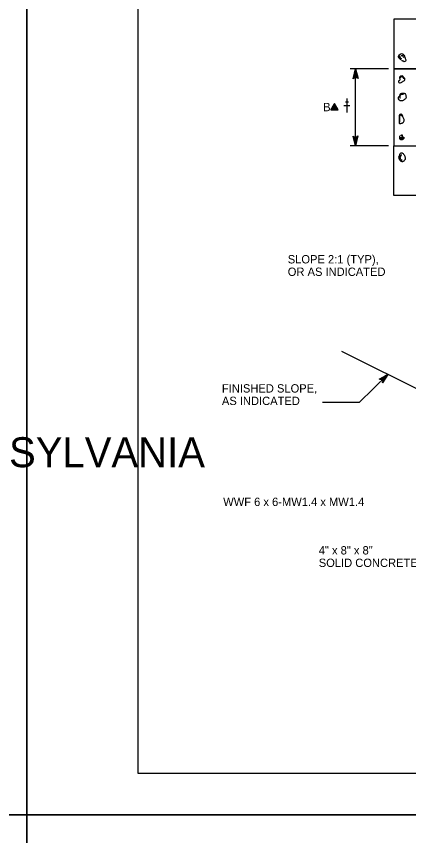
# Model space of a CAD drawing. Extents: x 636183 to 639890, y 299162 to 300538.
# Drawn here: x 638140.2 to 638281.4, y 299936.9 to 300231.9 of the extents above; entities that cross this region are included whole.
import ezdxf

# ---------------------------------------------------------------- set-up
doc = ezdxf.new("R2010")
doc.units = 0
for name, color, linetype in [('1', 7, 'Continuous'), ('Default', 7, 'Continuous'), ('PLT-BNDY', 7, 'Continuous')]:
    doc.layers.add(name, color=color, linetype=linetype)

# ---------------------------------------------------------------- blocks, each defined once
blk = doc.blocks.new('CT')
at = {"layer": 'Default'}
for p, q in [((-0.09, -0.28), (-0.27, 0.03)), ((-0.05, -0.28), (-0.25, 0.07)), ((-0.01, -0.28), (-0.23, 0.1)), ((0.03, -0.28), (-0.21, 0.14)), ((0.07, -0.28), (-0.19, 0.17)), ((0.11, -0.28), (-0.17, 0.21)), ((0.15, -0.28), (-0.15, 0.24)), ((0.19, -0.28), (-0.13, 0.28)), ((0.24, -0.28), (-0.11, 0.32)), ((0.28, -0.28), (-0.09, 0.35)), ((0.32, -0.28), (-0.07, 0.39)), ((0.36, -0.28), (-0.04, 0.42)), ((0.4, -0.28), (-0.02, 0.46)), ((0.44, -0.28), (0, 0.49)), ((-0.42, -0.28), (-0.44, -0.26)), ((-0.38, -0.28), (-0.42, -0.22)), ((-0.34, -0.28), (-0.39, -0.18)), ((-0.3, -0.28), (-0.37, -0.15)), ((-0.26, -0.28), (-0.35, -0.11)), ((-0.22, -0.28), (-0.33, -0.08)), ((-0.18, -0.28), (-0.31, -0.04)), ((-0.14, -0.28), (-0.29, -0.01))]:
    blk.add_line(p, q, dxfattribs=at)
blk.add_lwpolyline([(-0.45, -0.28), (0.44, -0.28), (0, 0.5)], close=True, dxfattribs=at)
blk = doc.blocks.new('CROSS')
at = {"layer": 'Default'}
for p, q in [((-0.182, 0), (0, 0)), ((-0.096, 0.218), (0, 0.218)), ((0, 0.436), (0, -0.435)), ((0, 0.436), (0, 0)), ((0, 0.218), (0.096, 0.218)), ((0, 0), (0.182, 0))]:
    blk.add_line(p, q, dxfattribs=at)

msp = doc.modelspace()

# ---------------------------------------------------------------- linework, layer by layer
at = {"layer": '1'}
msp.add_lwpolyline([(638969.91, 299959.45), (638969.91, 300523.45), (638183.91, 300523.45), (638183.91, 299959.45), (638969.91, 299959.45), (638969.91, 299985.81), (638769.91, 299985.81), (638769.91, 300050.49), (638969.91, 300050.49), (638969.91, 300079.45), (638769.91, 300079.45), (638769.91, 299959.45), (638848.72, 299959.45), (638848.72, 299985.81), (638848.72, 299959.45), (638925.72, 299959.45), (638925.72, 299985.81), (638925.72, 299973.49), (638969.91, 299973.49)], dxfattribs=at)
at = {"layer": 'Default'}
for p, q in [((638274.19, 300212.96), (638260.38, 300212.96)), ((638274.19, 300185.33), (638260.38, 300185.33)), ((638257.27, 300111.36), (638344.64, 300067.68))]:
    msp.add_line(p, q, dxfattribs=at)
for points in [[(638276.12, 300230.92), (638276.12, 300212.96), (638439.16, 300212.96), (638439.16, 300230.92), (638276.12, 300230.92)], [(638261.7, 300209.72), (638261.48, 300209.45), (638262.31, 300212.96), (638261.7, 300209.72), (638262.07, 300209.92), (638262.31, 300212.96), (638262.59, 300209.93), (638262.97, 300209.75), (638262.31, 300212.96), (638263.22, 300209.47), (638262.97, 300209.75)], [(638262.31, 300185.33), (638262.31, 300212.96)], [(638276.12, 300212.96), (638276.12, 300185.33), (638439.16, 300185.33), (638439.16, 300212.96), (638276.12, 300212.96)], [(638262.93, 300188.56), (638263.15, 300188.83), (638262.31, 300185.33), (638262.93, 300188.56), (638262.56, 300188.36), (638262.31, 300185.33), (638262.03, 300188.35), (638261.66, 300188.53), (638262.31, 300185.33), (638261.4, 300188.81), (638261.66, 300188.53)], [(638276.12, 300167.36), (638276.12, 300185.33), (638439.16, 300185.33), (638439.16, 300167.36), (638276.12, 300167.36)], [(638273.98, 300103.01), (638263.58, 300092.92), (638250.36, 300092.92)], [(638271.19, 300101.25), (638270.85, 300101.22), (638273.98, 300103.01), (638271.19, 300101.25), (638271.59, 300101.11), (638273.98, 300103.01), (638271.96, 300100.74), (638272.09, 300100.34), (638273.98, 300103.01), (638272.06, 300099.96), (638272.09, 300100.34)]]:
    msp.add_lwpolyline(points, dxfattribs=at)
for points, degree in [([(638278.67, 300216.24), (638278.37, 300216.43), (638278.14, 300216.68), (638277.94, 300216.97), (638277.77, 300217.23), (638277.79, 300217.61), (638277.94, 300217.88), (638278.03, 300218.04), (638278.16, 300218.16), (638278.31, 300218.25), (638278.63, 300218.44), (638279.11, 300218.51), (638279.4, 300218.25), (638279.8, 300217.89), (638279.97, 300217.43), (638280.13, 300216.97), (638280.27, 300216.58), (638280.49, 300215.94), (638280.13, 300215.69), (638279.87, 300215.51), (638279.5, 300215.75), (638279.22, 300215.88), (638279.1, 300215.94), (638278.97, 300215.99), (638278.86, 300216.06)], 3), ([(638278.92, 300216.59), (638278.69, 300216.73), (638278.51, 300216.92), (638278.36, 300217.15), (638278.26, 300217.3), (638278.27, 300217.54), (638278.36, 300217.71), (638278.37, 300217.72), (638278.37, 300217.72), (638278.38, 300217.73)], 3), ([(638278.76, 300217.83), (638278.89, 300217.85), (638279.03, 300217.91), (638279.16, 300217.83), (638279.41, 300217.66), (638279.45, 300217.38), (638279.56, 300217.13)], 3), ([(638279.13, 300210.53), (638279.31, 300210.41), (638279.44, 300210.26), (638279.58, 300210.08), (638279.8, 300209.79), (638280.06, 300209.47), (638280.03, 300209.18), (638279.99, 300208.82), (638279.48, 300208.54), (638279.13, 300208.29), (638278.76, 300208.03), (638277.98, 300207.94), (638277.79, 300208.29), (638277.64, 300208.55), (638278.18, 300208.86), (638278.23, 300209.18), (638278.29, 300209.47), (638278.01, 300209.84), (638278.23, 300210.08), (638278.49, 300210.35), (638278.81, 300210.44), (638279.13, 300210.53)], 3), ([(638278.5, 300209.89), (638278.5, 300209.9), (638278.5, 300209.91), (638278.5, 300209.91), (638278.68, 300210.17), (638278.96, 300210.2), (638279.22, 300210.28)], 3), ([(638279.02, 300210.26), (638279.16, 300210.17), (638279.26, 300210.06), (638279.36, 300209.92), (638279.48, 300209.77), (638279.58, 300209.6), (638279.6, 300209.45)], 3), ([(638278.22, 300203.47), (638278.27, 300204.07), (638279.54, 300204.38), (638279.86, 300204.2), (638280.25, 300203.99), (638280.69, 300202.45), (638280.04, 300202.01), (638279.63, 300201.74), (638279.2, 300201.5), (638278.76, 300201.47), (638278.59, 300201.46), (638278.4, 300201.52), (638278.22, 300201.65), (638277.71, 300202.01), (638277.71, 300203.09), (638278.22, 300203.29)], 3), ([(638278.43, 300203.33), (638278.47, 300203.76), (638279.38, 300203.98), (638279.62, 300203.85)], 2), ([(638278.44, 300202.44), (638278.38, 300202.67), (638278.23, 300203), (638278.44, 300203.13)], 2), ([(638278.03, 300196.18), (638278.17, 300196.46), (638278.57, 300196.87), (638278.76, 300196.72), (638279.07, 300196.48), (638279.3, 300195.92), (638279.49, 300195.45), (638279.69, 300194.97), (638279.92, 300194.45), (638279.68, 300193.99), (638279.52, 300193.7), (638279.22, 300193.54), (638278.95, 300193.44), (638278.67, 300193.33), (638278.03, 300193.31), (638278.03, 300193.62), (638278.03, 300193.99), (638278.03, 300194.35), (638278.03, 300194.72), (638278.03, 300195.2), (638278.03, 300195.69), (638278.03, 300196.18)], 3), ([(638278.25, 300196.03), (638278.33, 300196.2), (638278.58, 300196.46), (638278.69, 300196.36), (638278.77, 300196.28), (638278.83, 300196.13), (638278.89, 300196.01)], 3), ([(638278.28, 300193.83), (638278.28, 300194.12), (638278.28, 300194.42), (638278.28, 300194.72), (638278.28, 300195.2), (638278.28, 300195.69), (638278.28, 300196.18)], 3), ([(638278.58, 300188.88), (638278.64, 300189.05), (638278.85, 300189.19), (638278.95, 300189.24), (638279.13, 300189.36), (638279.15, 300188.44), (638279.31, 300188.33), (638279.37, 300188.29), (638279.64, 300188.41), (638279.68, 300188.33), (638279.73, 300188.2), (638279.65, 300187.93), (638279.49, 300187.78), (638279.32, 300187.62), (638279.14, 300187.47), (638278.95, 300187.42), (638278.78, 300187.38), (638278.48, 300187.41), (638278.4, 300187.6), (638278.21, 300188.03), (638278.25, 300188.45), (638278.22, 300188.88)], 3), ([(638278.87, 300188.39), (638278.91, 300188.53), (638279.1, 300188.06), (638279.05, 300187.95), (638279.02, 300187.91), (638278.95, 300187.87), (638278.89, 300187.85), (638278.84, 300187.84), (638278.77, 300187.85), (638278.75, 300187.9), (638278.68, 300188.06), (638278.69, 300188.23), (638278.68, 300188.39)], 3), ([(638278.13, 300181.4), (638278.16, 300181.71), (638278.21, 300182.01), (638278.31, 300182.31), (638278.42, 300182.67), (638279.15, 300182.79), (638279.4, 300182.49), (638279.78, 300182.06), (638280.05, 300181.55), (638280.13, 300181.03), (638280.18, 300180.74), (638280.2, 300180.42), (638279.95, 300180.12), (638279.67, 300179.79), (638279.33, 300179.54), (638279.04, 300179.58), (638278.79, 300179.61), (638278.5, 300179.83), (638278.31, 300180.12), (638278.03, 300180.55), (638278.02, 300180.96), (638277.94, 300181.4)], 3), ([(638279.06, 300180.08), (638278.92, 300180.1), (638278.77, 300180.22), (638278.67, 300180.37), (638278.43, 300180.74), (638278.41, 300181.11), (638278.35, 300181.49)], 3), ([(638278.53, 300181.34), (638278.56, 300181.55), (638278.58, 300181.75), (638278.66, 300181.95), (638278.69, 300182.04), (638278.86, 300182.06), (638278.93, 300182)], 3)]:
    msp.add_open_spline(points, degree=degree, dxfattribs=at)
at = {"layer": 'PLT-BNDY'}
for points in [[(637302.91, 300538.45), (638143.91, 300538.45), (638143.91, 299944.45), (637302.91, 299944.45)], [(638143.91, 300538.45), (638984.91, 300538.45), (638984.91, 299944.45), (638143.91, 299944.45)], [(637302.91, 299944.45), (638143.91, 299944.45), (638143.91, 299350.45), (637302.91, 299350.45)], [(638143.91, 299944.45), (638984.91, 299944.45), (638984.91, 299350.45), (638143.91, 299350.45)]]:
    msp.add_lwpolyline(points, close=True, dxfattribs=at)

# ---------------------------------------------------------------- block references
at = {"layer": 'Default'}
for name, p, xscale, yscale in [('CROSS', (638259.2, 300199.82), 5.80239905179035, 5.80239905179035), ('CT', (638254.73, 300199.1), 2.901199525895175, 2.901199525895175)]:
    msp.add_blockref(name, p, dxfattribs=dict(at, xscale=xscale, yscale=yscale))

# ---------------------------------------------------------------- texts
at = {"layer": '1'}
msp.add_text('COMMONWEALTH OF PENNSYLVANIA', height=10.7834, dxfattribs=at).set_placement((637942.07, 300069.59))
at = {"layer": 'Default'}
for s, height, p in [('B', 3, (638250.65, 300197.75)), ('SLOPE 2:1 (TYP),', 2.998, (638237.9, 300142.95)), ('OR AS INDICATED', 2.998, (638237.9, 300138.45)), ('FINISHED SLOPE,', 2.998, (638214.19, 300096.46)), ('AS INDICATED', 2.998, (638214.19, 300091.97)), ('WWF 6 x 6-MW1.4 x MW1.4', 2.998, (638214.66, 300055.62)), ('4" x 8" x 8"', 2.998, (638249.06, 300038.16)), ('SOLID CONCRETE BLOCKS', 2.998, (638249.06, 300033.67))]:
    msp.add_text(s, height=height, dxfattribs=at).set_placement(p)

doc.saveas('drawing.dxf')
